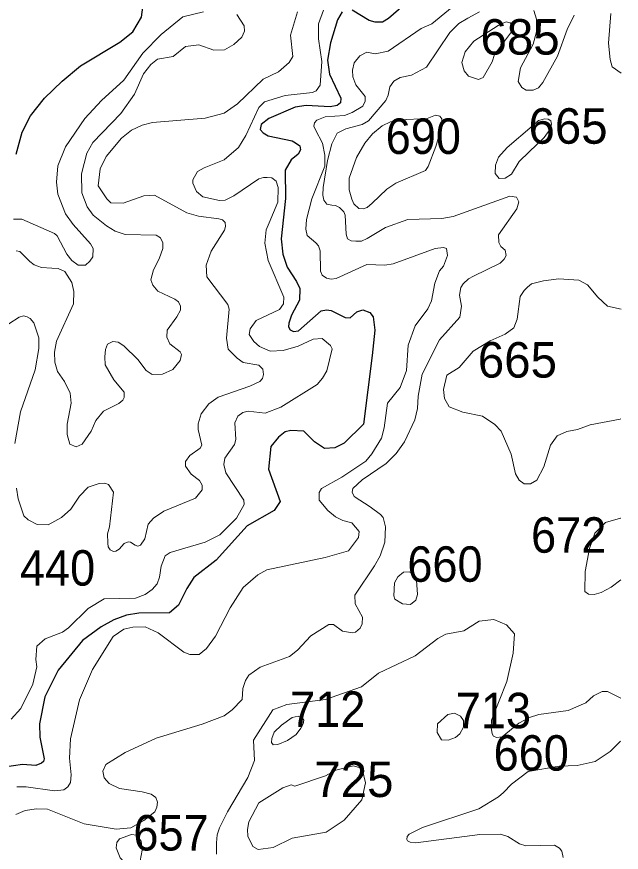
# Model space of a CAD drawing. Extents: x 499.9 to 555.3, y 9281.5 to 9336.8.
# Drawn here: x 552.609 to 555.335, y 9330.074 to 9333.844 of the extents above; entities that cross this region are included whole.
import ezdxf
from ezdxf.enums import TextEntityAlignment as Align

# ---------------------------------------------------------------- set-up
doc = ezdxf.new("R2010")
doc.units = 0
doc.header["$LTSCALE"] = 0.064
doc.layers.add('1', color=7, linetype='Continuous', lineweight=25)
doc.layers.add('2', color=7, linetype='Continuous', lineweight=13)
doc.layers.add('21', color=7, linetype='Continuous')

msp = doc.modelspace()

# ---------------------------------------------------------------- linework, layer by layer
at = {"layer": '1'}
for points in [[(552.6067, 9333.2243), (552.6336, 9333.3236), (552.6713, 9333.3965), (552.7348, 9333.4764), (552.8144, 9333.5542), (552.8965, 9333.6221), (553.074, 9333.7299), (553.1324, 9333.7757), (553.1716, 9333.8418), (553.1865, 9333.9546)], [(554.3535, 9333.8949), (554.2849, 9333.8357), (554.2586, 9333.8202), (554.2249, 9333.8203), (554.1978, 9333.8268), (554.1207, 9333.8737)], [(554.0767, 9333.8658), (554.0547, 9333.8301), (554.023, 9333.7261), (554.0107, 9333.6479), (554.0184, 9333.5847), (554.0702, 9333.4764), (554.0684, 9333.4558), (554.0538, 9333.4437), (554.0218, 9333.4383), (553.9136, 9333.4435), (553.8644, 9333.4359), (553.7452, 9333.3858), (553.7105, 9333.3588), (553.7072, 9333.3361), (553.7204, 9333.3211), (553.7421, 9333.3072), (553.8508, 9333.2849), (553.8653, 9333.2759), (553.8853, 9333.2614), (553.8884, 9333.2433), (553.8778, 9333.2235), (553.8468, 9333.199), (553.8197, 9333.1516), (553.821, 9333.0248), (553.8008, 9332.842), (553.8082, 9332.773), (553.8289, 9332.7141), (553.8703, 9332.6497), (553.8847, 9332.6183), (553.8844, 9332.5647), (553.8484, 9332.4984), (553.8359, 9332.461), (553.8338, 9332.4455), (553.8419, 9332.431), (553.8563, 9332.4238), (553.879, 9332.4277), (553.9812, 9332.5174), (554.0056, 9332.5213), (554.0265, 9332.5188), (554.0894, 9332.4878), (554.1125, 9332.4859), (554.1418, 9332.513), (554.1697, 9332.5219), (554.2013, 9332.5094), (554.2155, 9332.4903), (554.2235, 9332.4305), (554.2111, 9332.3155), (554.1723, 9332.0061), (554.0855, 9331.9206), (554.0438, 9331.8994), (553.9962, 9331.8964), (553.9508, 9331.9267), (553.903, 9331.9747), (553.8451, 9331.9779), (553.8186, 9331.9712), (553.7889, 9331.9471), (553.7546, 9331.9047)], [(553.7546, 9331.9047), (553.7436, 9331.8022), (553.7968, 9331.6573), (553.769, 9331.6159), (553.6477, 9331.5466), (553.5076, 9331.3924)], [(553.5076, 9331.3924), (553.408, 9331.3147), (553.3757, 9331.265), (553.3388, 9331.1888), (553.2981, 9331.1543), (553.1588, 9331.1533), (553.1042, 9331.1441), (553.0469, 9331.1236), (552.9897, 9331.0911), (552.9051, 9331.0299), (552.7963, 9330.8958), (552.7358, 9330.7748), (552.7119, 9330.6538), (552.7135, 9330.5934), (552.7333, 9330.4961), (552.729, 9330.484), (552.72, 9330.476), (552.695, 9330.4663), (552.6346, 9330.4707), (552.5542, 9330.4579), (552.47, 9330.4055), (552.4038, 9330.3336), (552.324, 9330.211), (552.2507, 9330.0626)]]:
    msp.add_lwpolyline(points, dxfattribs=at)
at = {"layer": '2'}
for points in [[(554.7064, 9333.9986), (554.4807, 9333.8126), (554.4318, 9333.7908), (554.283, 9333.6884), (554.2244, 9333.6775), (554.1869, 9333.6842), (554.1552, 9333.6685), (554.1301, 9333.6364), (554.1229, 9333.6028), (554.1242, 9333.5735), (554.1381, 9333.5375), (554.1797, 9333.4847), (554.1798, 9333.4639), (554.1693, 9333.4414), (554.122, 9333.4116), (554.0868, 9333.3987), (554.0003, 9333.3928), (553.9622, 9333.378), (553.9515, 9333.3653), (553.9491, 9333.3504), (553.9555, 9333.3336), (553.9875, 9333.2737), (553.9979, 9333.2203), (553.998, 9333.1697), (553.9395, 9333.0219), (553.9154, 9332.9288), (553.912, 9332.8861), (553.9186, 9332.8569), (553.9574, 9332.8236), (553.9694, 9332.8112), (553.9763, 9332.7881), (553.9781, 9332.6959), (553.9864, 9332.6782), (554.005, 9332.6651), (554.0267, 9332.6596), (554.0495, 9332.6628), (554.1882, 9332.7257), (554.2692, 9332.7231), (554.3066, 9332.7293), (554.4952, 9332.7978), (554.5325, 9332.8038), (554.5467, 9332.799), (554.5515, 9332.7674), (554.533, 9332.7195), (554.5153, 9332.698), (554.4935, 9332.6419), (554.4796, 9332.563), (554.4625, 9332.5257), (554.4058, 9332.4498), (554.3734, 9332.3624), (554.3667, 9332.2479), (554.3379, 9332.1716), (554.2811, 9332.1013), (554.2661, 9331.9896), (554.254, 9331.9432), (554.2106, 9331.8714), (554.1824, 9331.8396), (554.0754, 9331.7665), (553.9832, 9331.716), (553.9728, 9331.6969)], [(553.9921, 9333.8742), (553.9692, 9333.8122), (553.9699, 9333.7453), (553.9849, 9333.642), (553.9775, 9333.5353), (553.9594, 9333.5099), (553.9419, 9333.5025), (553.8196, 9333.4884), (553.7267, 9333.4607), (553.7003, 9333.4344), (553.6421, 9333.3078), (553.6088, 9333.254), (553.5437, 9333.1983), (553.4545, 9333.1629), (553.4247, 9333.1453), (553.403, 9333.1085), (553.4026, 9333.0935), (553.4192, 9333.055), (553.4479, 9333.0315), (553.5235, 9333.0158), (553.548, 9333.0162), (553.5874, 9333.0358), (553.7004, 9333.113), (553.7211, 9333.1183), (553.7384, 9333.1195), (553.7597, 9333.1168), (553.7787, 9333.1018), (553.7883, 9333.0745), (553.7867, 9333.0078), (553.7466, 9332.9149), (553.7336, 9332.8827), (553.7273, 9332.8224), (553.742, 9332.7445), (553.813, 9332.5795), (553.8115, 9332.5486), (553.7933, 9332.5235), (553.6889, 9332.4741), (553.6607, 9332.4364), (553.6576, 9332.411), (553.6784, 9332.3782), (553.7034, 9332.357), (553.751, 9332.3346), (553.8107, 9332.338), (553.8784, 9332.3585), (553.9462, 9332.3898), (553.9863, 9332.3926), (554.0232, 9332.3613), (554.031, 9332.3457), (554.0072, 9332.2471), (553.9881, 9332.2135), (553.9628, 9332.185), (553.799, 9332.0823), (553.729, 9332.055), (553.6525, 9332.064), (553.6288, 9332.0586), (553.6062, 9332.0424), (553.5923, 9332.0123), (553.5965, 9331.9367), (553.5914, 9331.9141), (553.5466, 9331.8532), (553.5429, 9331.8236), (553.5523, 9331.7864), (553.6331, 9331.6629), (553.6348, 9331.6437)], [(555.1223, 9333.8512), (555.0913, 9333.786), (555.0473, 9333.6666), (554.9814, 9333.5474), (554.9613, 9333.5231), (554.9368, 9333.5126), (554.9063, 9333.513), (554.8864, 9333.5247), (554.8697, 9333.5521), (554.881, 9333.6135), (554.937, 9333.7199), (554.9525, 9333.7759), (554.9526, 9333.8338), (554.9401, 9333.8727)], [(552.5947, 9332.9302), (552.6321, 9332.9313), (552.7794, 9332.8656), (552.7907, 9332.855), (552.835, 9332.7733), (552.8567, 9332.7437), (552.8856, 9332.7239), (552.9197, 9332.7238), (552.9389, 9332.7409), (552.9517, 9332.7616), (552.9532, 9332.7982), (552.9417, 9332.8203), (552.8637, 9332.9067), (552.8281, 9332.9553), (552.7947, 9333.0444), (552.7882, 9333.0982), (552.7941, 9333.1716), (552.8293, 9333.2569), (552.9154, 9333.3856), (552.991, 9333.4667), (553.0921, 9333.5585), (553.1774, 9333.6798), (553.2607, 9333.7635), (553.3575, 9333.8444), (553.4506, 9333.8664)], [(552.8646, 9332.5485), (552.7886, 9332.3799), (552.7788, 9332.3307), (552.7805, 9332.2861), (552.7925, 9332.244), (552.8248, 9332.1977), (552.8492, 9332.1464), (552.8547, 9332.1004), (552.8361, 9332.006), (552.8361, 9331.9597), (552.848, 9331.9158), (552.8773, 9331.9037), (552.9032, 9331.915), (552.9441, 9331.9748), (552.9663, 9332.022), (553.0003, 9332.064), (553.0691, 9332.0998), (553.0867, 9332.1145), (553.0934, 9332.1256), (553.0929, 9332.151), (553.0461, 9332.2057), (553.0082, 9332.2736), (553.0064, 9332.3099), (553.0087, 9332.3423), (553.0189, 9332.367), (553.0423, 9332.3787), (553.0667, 9332.3762), (553.092, 9332.3596), (553.1543, 9332.2979), (553.1926, 9332.2487), (553.219, 9332.2301), (553.2657, 9332.2313), (553.3131, 9332.2518), (553.3451, 9332.2932), (553.3512, 9332.3195), (553.3456, 9332.3325), (553.2991, 9332.3691), (553.2856, 9332.3977), (553.2879, 9332.4299), (553.3309, 9332.4906), (553.3466, 9332.5196), (553.3479, 9332.5382), (553.3387, 9332.5573), (553.3213, 9332.5699), (553.2447, 9332.6059), (553.2219, 9332.6325), (553.2133, 9332.6573), (553.2253, 9332.7022), (553.2516, 9332.7523), (553.2674, 9332.7979), (553.2683, 9332.8236), (553.2575, 9332.8464), (553.2377, 9332.8581), (553.0978, 9332.8614), (553.0525, 9332.8773), (553.0136, 9332.9001), (552.9532, 9332.9496), (552.9262, 9332.9871), (552.9027, 9333.0494), (552.9012, 9333.136), (552.9249, 9333.2282), (552.9527, 9333.2773), (553.0786, 9333.407), (553.1404, 9333.4947), (553.1809, 9333.5871), (553.2133, 9333.6284), (553.2437, 9333.6528), (553.3145, 9333.6651), (553.3702, 9333.7106), (553.4303, 9333.7173), (553.4982, 9333.6939), (553.5458, 9333.6956), (553.5872, 9333.7193), (553.6236, 9333.7528), (553.6359, 9333.7797), (553.6345, 9333.8027), (553.6019, 9333.8537)], [(553.202, 9331.554), (553.226, 9331.5816), (553.2729, 9331.6138), (553.4145, 9331.6721), (553.4449, 9331.7101), (553.4447, 9331.7303), (553.4332, 9331.7513), (553.3947, 9331.7807), (553.3697, 9331.8158), (553.3701, 9331.8373), (553.3901, 9331.8648), (553.4353, 9331.898), (553.4436, 9331.9114), (553.4265, 9331.9812), (553.4266, 9332.0067), (553.4409, 9332.0526), (553.475, 9332.0978), (553.5166, 9332.1271), (553.6604, 9332.1772), (553.7057, 9332.198), (553.7177, 9332.2121), (553.722, 9332.2306), (553.7179, 9332.2545), (553.7006, 9332.2718), (553.6304, 9332.2846), (553.6026, 9332.3034), (553.5621, 9332.3443), (553.554, 9332.3937), (553.5674, 9332.5242), (553.56, 9332.5453), (553.4661, 9332.6703), (553.4625, 9332.7231), (553.4858, 9332.7872), (553.5453, 9332.8814), (553.5503, 9332.8978), (553.5487, 9332.9161), (553.5374, 9332.9283), (553.5196, 9332.933), (553.4284, 9332.9451), (553.3764, 9332.9588), (553.2307, 9333.0393), (553.1822, 9333.0361), (553.0881, 9333.0034), (553.0335, 9333.005), (553.0152, 9333.022), (552.9763, 9333.0811), (552.9855, 9333.1582), (553.0127, 9333.213), (553.0817, 9333.2963), (553.1264, 9333.3327), (553.1742, 9333.3549), (553.2204, 9333.3672), (553.4592, 9333.3865), (553.5441, 9333.4098), (553.6037, 9333.4508), (553.7203, 9333.5626), (553.7894, 9333.5962), (553.837, 9333.6381), (553.8541, 9333.6644), (553.8437, 9333.7611), (553.8746, 9333.8661)], [(554.6956, 9333.8659), (554.6424, 9333.8386), (554.6028, 9333.814), (554.562, 9333.7731), (554.4564, 9333.6168), (554.3882, 9333.5813), (554.3372, 9333.5705), (554.3099, 9333.5532), (554.291, 9333.5277), (554.2832, 9333.4911), (554.2736, 9333.4671), (554.1945, 9333.3751), (554.1665, 9333.3574), (554.0934, 9333.3387), (554.0533, 9333.3189), (554.0298, 9333.2708), (554.0098, 9333.1956), (553.9904, 9333.0733), (553.9888, 9333.0385), (553.9942, 9333.0164), (554.0072, 9332.9986), (554.0291, 9332.9942), (554.0468, 9332.9926), (554.0639, 9332.9839), (554.0831, 9332.9637), (554.0896, 9332.9482), (554.0936, 9332.8628), (554.101, 9332.8423), (554.1162, 9332.8329), (554.1379, 9332.8314), (554.1629, 9332.8313), (554.1888, 9332.844), (554.2717, 9332.8932), (554.3716, 9332.9293), (554.5262, 9332.9346), (554.5764, 9332.9425), (554.8318, 9333.0346), (554.8619, 9333.0302), (554.8728, 9333.0093), (554.8635, 9332.9776), (554.7811, 9332.8596), (554.7828, 9332.8249), (554.7914, 9332.8076), (554.8109, 9332.7913), (554.8157, 9332.7663), (554.8066, 9332.7498), (554.788, 9332.7321), (554.6689, 9332.673), (554.6462, 9332.6621), (554.6225, 9332.639), (554.611, 9332.6226), (554.606, 9332.5884), (554.6136, 9332.5383), (554.6074, 9332.4882), (554.5148, 9332.3863), (554.4368, 9332.2308), (554.4182, 9332.1316), (554.4162, 9332.076), (554.4036, 9332.0259), (554.3568, 9331.9257), (554.3193, 9331.8731), (554.2753, 9331.829), (554.1666, 9331.7551), (554.1243, 9331.7151), (554.1215, 9331.6985), (554.1297, 9331.6795)], [(555.3347, 9333.5892), (555.2943, 9333.6186), (555.2842, 9333.6512), (555.2774, 9333.7254), (555.287, 9333.8594)], [(552.6066, 9332.7876), (552.623, 9332.7844), (552.668, 9332.74), (552.6874, 9332.7249), (552.7207, 9332.7122), (552.7668, 9332.7099)], [(552.7668, 9332.7099), (552.7961, 9332.7081), (552.8251, 9332.6947), (552.858, 9332.6448), (552.8671, 9332.605), (552.8646, 9332.5485)], [(555.3332, 9332.0294), (555.33, 9332.0288), (555.1941, 9332.0034), (555.1374, 9331.9822), (555.0889, 9331.9729), (555.0453, 9331.9539), (555.015, 9331.911), (554.9848, 9331.8133), (554.9545, 9331.7527), (554.9248, 9331.7366), (554.8972, 9331.7362), (554.8748, 9331.7527), (554.8576, 9331.7817), (554.8378, 9331.8706), (554.7935, 9331.9748), (554.7643, 9332.004), (554.7094, 9332.0424), (554.621, 9332.0595), (554.5587, 9332.0846), (554.5375, 9332.1214), (554.5328, 9332.1626), (554.5489, 9332.2277), (554.6041, 9332.2615), (554.6669, 9332.3358), (554.7434, 9332.3812), (554.8117, 9332.4118), (554.8501, 9332.4399), (554.8657, 9332.4794), (554.8794, 9332.5821), (554.8973, 9332.6084), (554.9114, 9332.6246), (554.9299, 9332.6386), (554.9842, 9332.6533), (555.053, 9332.6623), (555.1429, 9332.656), (555.1819, 9332.6351), (555.2292, 9332.5786), (555.273, 9332.5385), (555.3337, 9332.5246)], [(552.5729, 9332.4581), (552.6196, 9332.4885), (552.6394, 9332.494), (552.6565, 9332.4895), (552.6698, 9332.4821), (552.6862, 9332.4633), (552.7084, 9332.3958), (552.7086, 9332.3473), (552.6925, 9332.2511), (552.6261, 9332.0616), (552.6005, 9331.9183)], [(552.6076, 9331.7173), (552.6147, 9331.6696), (552.6406, 9331.5928), (552.661, 9331.5745), (552.7017, 9331.5536), (552.7507, 9331.5521), (552.8113, 9331.5846), (552.8522, 9331.622), (552.8922, 9331.681), (552.9317, 9331.7216), (552.9799, 9331.7377), (553.0055, 9331.7392), (553.0225, 9331.7334), (553.0458, 9331.6994), (553.0266, 9331.5422), (553.0176, 9331.5108), (553.019, 9331.469), (553.0218, 9331.4522), (553.0309, 9331.4382), (553.0445, 9331.4315), (553.0564, 9331.4334), (553.0709, 9331.4416), (553.0935, 9331.4681), (553.1116, 9331.4746), (553.1215, 9331.4734)], [(553.9728, 9331.6969), (553.9729, 9331.6627), (554.0122, 9331.6166), (554.0469, 9331.5881), (554.08, 9331.571), (554.1193, 9331.5604)], [(554.1297, 9331.6795), (554.2023, 9331.6334), (554.2492, 9331.5985), (554.261, 9331.5843), (554.2713, 9331.5419), (554.2689, 9331.4738)], [(553.6348, 9331.6437), (553.5999, 9331.5818), (553.5241, 9331.5069), (553.4584, 9331.4727), (553.3, 9331.4274), (553.2786, 9331.4111)], [(555.3326, 9331.3035), (555.2893, 9331.2702), (555.2437, 9331.2463), (555.2121, 9331.2377), (555.1868, 9331.2389), (555.1711, 9331.2512), (555.1724, 9331.3405), (555.1917, 9331.4454), (555.2158, 9331.5147), (555.2642, 9331.5619), (555.3318, 9331.5817), (555.3328, 9331.582)], [(554.1193, 9331.5604), (554.1531, 9331.5208), (554.1504, 9331.4943), (554.1046, 9331.434), (553.9997, 9331.4043), (553.7361, 9331.3491), (553.6963, 9331.3259), (553.6298, 9331.269), (553.572, 9331.1775), (553.5048, 9331.0493), (553.4652, 9330.9943), (553.4311, 9330.9663), (553.3891, 9330.966), (553.363, 9330.9775), (553.2467, 9331.064), (553.1885, 9331.0914), (553.1329, 9331.0899), (553.0914, 9331.0805), (553.0439, 9331.0477), (552.9507, 9330.8989), (552.8922, 9330.762), (552.8519, 9330.5863), (552.8472, 9330.4987), (552.8548, 9330.4243), (552.8509, 9330.3885), (552.8388, 9330.3695), (552.8216, 9330.3558), (552.7793, 9330.3518), (552.6514, 9330.3689), (552.6087, 9330.3689)], [(553.1215, 9331.4734), (553.1423, 9331.4594), (553.1556, 9331.4561), (553.1668, 9331.4597), (553.186, 9331.4879), (553.202, 9331.554)], [(554.2689, 9331.4738), (554.2479, 9331.4111), (554.2219, 9331.3673), (554.1338, 9331.2346), (554.1355, 9331.1954), (554.1674, 9331.1346), (554.167, 9331.1042), (554.1579, 9331.0847), (554.1365, 9331.0676), (554.1225, 9331.0641), (554.077, 9331.0719), (554.0368, 9331.1012), (554.0159, 9331.1013), (553.9343, 9331.0501), (553.8741, 9330.9854), (553.8386, 9330.9579), (553.7066, 9330.9092), (553.6553, 9330.873), (553.6398, 9330.8495), (553.6288, 9330.8137), (553.6251, 9330.7637), (553.5808, 9330.7176), (553.5442, 9330.6905), (553.4455, 9330.6517), (553.2378, 9330.5889), (553.0977, 9330.5237), (553.0111, 9330.4703), (552.997, 9330.44), (553.0031, 9330.4095), (553.026, 9330.3845), (553.0721, 9330.3612), (553.1746, 9330.3463), (553.2146, 9330.3358), (553.2368, 9330.3214), (553.2429, 9330.3005), (553.2407, 9330.2781), (553.2317, 9330.2572), (553.1822, 9330.2181), (553.1236, 9330.1838), (553.0566, 9330.1781), (552.9132, 9330.2019), (552.7475, 9330.2681), (552.6983, 9330.2708), (552.6475, 9330.262), (552.6044, 9330.2451)], [(553.2786, 9331.4111), (553.2597, 9331.3645), (553.253, 9331.3149), (553.242, 9331.2849), (553.22, 9331.2592), (553.1876, 9331.2374), (553.1447, 9331.2201), (553.0033, 9331.2171), (552.9306, 9331.1744), (552.8423, 9331.0868), (552.8151, 9331.0671), (552.7375, 9331.0373), (552.6998, 9331.0044), (552.6943, 9330.9439), (552.6989, 9330.9109), (552.6821, 9330.8322), (552.6274, 9330.7224), (552.5845, 9330.6746)], [(553.5102, 9330.065), (553.5091, 9330.1162), (553.513, 9330.1531), (553.5232, 9330.1839), (553.5585, 9330.2561), (553.6508, 9330.412), (553.681, 9330.4884), (553.6768, 9330.5797), (553.7635, 9330.7173), (553.8267, 9330.7412), (554.0011, 9330.7641), (554.1631, 9330.8206), (554.2402, 9330.8818), (554.4052, 9330.9611), (554.507, 9331.039), (554.5431, 9331.0577), (554.6241, 9331.0739), (554.6943, 9331.1165), (554.7602, 9331.1248), (554.8174, 9331.1003), (554.8538, 9331.0604), (554.8478, 9330.973), (554.8186, 9330.8444), (554.7496, 9330.6701), (554.7477, 9330.6367), (554.7524, 9330.6079), (554.7586, 9330.5978), (554.7718, 9330.5927), (554.7979, 9330.5948), (554.8731, 9330.6561), (554.921, 9330.6825), (554.9623, 9330.6952), (555.0952, 9330.7142), (555.1746, 9330.7483), (555.2091, 9330.7795), (555.2489, 9330.8), (555.2733, 9330.7997), (555.3321, 9330.7691)], [(555.3319, 9330.5762), (555.3317, 9330.576), (555.285, 9330.5294), (555.2164, 9330.4842), (555.1355, 9330.465), (555.054, 9330.463), (554.9144, 9330.4386), (554.8401, 9330.3813), (554.8039, 9330.3436), (554.7818, 9330.324), (554.6924, 9330.27), (554.4379, 9330.1861), (554.379, 9330.1558), (554.3695, 9330.1446), (554.3682, 9330.1324), (554.3703, 9330.1256), (554.3821, 9330.1191), (554.4077, 9330.116), (554.6966, 9330.1543), (554.7904, 9330.1556), (554.823, 9330.1458), (554.8765, 9330.1129), (554.9051, 9330.1033), (555.0336, 9330.1057), (555.0565, 9330.0921), (555.0672, 9330.079), (555.0725, 9330.0506)]]:
    msp.add_lwpolyline(points, dxfattribs=at)
for points in [[(554.6457, 9333.576), (554.6267, 9333.6009), (554.6163, 9333.6383), (554.6312, 9333.6863), (554.6694, 9333.7348), (554.7791, 9333.8047), (554.8159, 9333.8214), (554.8342, 9333.8173), (554.8443, 9333.8074), (554.8442, 9333.7827), (554.7624, 9333.6736), (554.7521, 9333.6415), (554.7114, 9333.5708), (554.6909, 9333.5605)], [(554.1191, 9333.0211), (554.1073, 9333.0632), (554.1083, 9333.1165), (554.1414, 9333.2086), (554.1779, 9333.2742), (554.2128, 9333.3165), (554.2566, 9333.3526), (554.2947, 9333.3707), (554.3384, 9333.3786), (554.4593, 9333.3845), (554.4975, 9333.4004), (554.5166, 9333.3957), (554.5258, 9333.3831), (554.5277, 9333.3508), (554.5139, 9333.3094), (554.4991, 9333.2594), (554.4634, 9333.1684), (554.4513, 9333.1512), (554.3187, 9333.0933), (554.2774, 9333.0661), (554.211, 9333.0031), (554.1895, 9332.9837), (554.1704, 9332.9781), (554.1518, 9332.9784), (554.1291, 9333.0006)], [(554.9329, 9333.3505), (554.8195, 9333.2549), (554.7808, 9333.2105), (554.7673, 9333.1752), (554.7668, 9333.137), (554.7843, 9333.1145), (554.8116, 9333.1155), (554.84, 9333.1334), (554.8739, 9333.1905), (554.9199, 9333.234), (554.9877, 9333.2987), (555.0148, 9333.3377), (555.0208, 9333.3597), (555.0172, 9333.3739), (555.0053, 9333.3823), (554.9898, 9333.3839), (554.9621, 9333.3768)], [(554.3087, 9331.2309), (554.3124, 9331.2894), (554.3268, 9331.3164), (554.353, 9331.3375), (554.3778, 9331.3403), (554.3961, 9331.3322), (554.411, 9331.3022), (554.4165, 9331.2377), (554.4089, 9331.2119), (554.3851, 9331.1922), (554.3483, 9331.1959), (554.3135, 9331.216)], [(553.7587, 9330.5868), (553.7699, 9330.616), (553.8024, 9330.6477), (553.8514, 9330.6824), (553.878, 9330.6876), (553.8959, 9330.6811), (553.9032, 9330.6705), (553.9007, 9330.6542), (553.8902, 9330.6339), (553.869, 9330.6055), (553.8292, 9330.5778), (553.7863, 9330.5602), (553.7657, 9330.5583), (553.758, 9330.5693)], [(554.5243, 9330.581), (554.5536, 9330.5796), (554.5873, 9330.5917), (554.6068, 9330.6082), (554.6235, 9330.6384), (554.6227, 9330.6686), (554.6092, 9330.688), (554.5821, 9330.7022), (554.5523, 9330.6962), (554.5068, 9330.6537), (554.5048, 9330.6147)], [(554.0035, 9330.1645), (554.0848, 9330.2191), (554.165, 9330.3112), (554.1822, 9330.3873), (554.1673, 9330.4444), (554.1575, 9330.4552), (554.1277, 9330.4642), (554.0484, 9330.444), (554.0012, 9330.4196), (553.8621, 9330.3723), (553.8465, 9330.3779), (553.8085, 9330.3648), (553.7002, 9330.2978), (553.6561, 9330.2121), (553.6499, 9330.1776), (553.6509, 9330.1475), (553.6739, 9330.0997), (553.698, 9330.0861), (553.7655, 9330.0954), (553.8507, 9330.1379)], [(553.0756, 9330.0485), (553.0944, 9330.0287), (553.1147, 9330.0218), (553.1469, 9330.0244), (553.1659, 9330.0356), (553.1747, 9330.0831), (553.1703, 9330.1242), (553.1496, 9330.1513), (553.1268, 9330.1549), (553.0719, 9330.1353), (553.0609, 9330.1181), (553.0578, 9330.0935)]]:
    msp.add_lwpolyline(points, close=True, dxfattribs=at)

# ---------------------------------------------------------------- texts
at = {"layer": '21'}
for s, p in [('685', (554.6999, 9333.6734)), ('665', (554.9162, 9333.2713)), ('725', (553.9508, 9330.3234))]:
    msp.add_text(s, height=0.16, dxfattribs=at).set_placement(p)
at = {"layer": '21', "width": 0.95}
for s, p in [('690', (554.2726, 9333.2253)), ('440', (552.6235, 9331.2773)), ('660', (554.3703, 9331.2946)), ('712', (553.8417, 9330.6395)), ('713', (554.5887, 9330.6337)), ('657', (553.1349, 9330.0821))]:
    msp.add_text(s, height=0.16, dxfattribs=at).set_placement(p)
at = {"layer": '21'}
msp.add_text('665', height=0.16, dxfattribs=at).set_placement((555.0449, 9332.216), align=Align.RIGHT)
at = {"layer": '21', "width": 0.95}
for s, p in [('672', (555.2672, 9331.4258)), ('660', (555.0984, 9330.4424))]:
    msp.add_text(s, height=0.16, dxfattribs=at).set_placement(p, align=Align.RIGHT)

doc.saveas('drawing.dxf')
